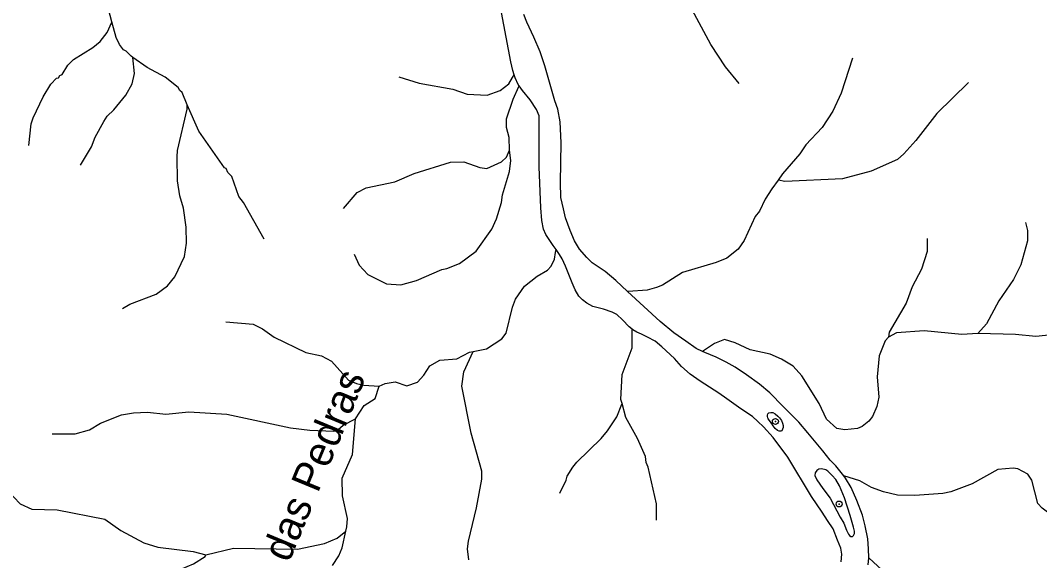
# Model space of a CAD drawing. Extents: x 393 to 446.6, y 8175.5 to 8231.
# Drawn here: x 438.18 to 443.66, y 8202.28 to 8205.18 of the extents above; entities that cross this region are included whole.
import ezdxf
from ezdxf.enums import TextEntityAlignment as Align

# ---------------------------------------------------------------- set-up
doc = ezdxf.new("R2010")
doc.units = 0
doc.header["$LTSCALE"] = 0.064
doc.header["$PDMODE"] = 32
doc.header["$PDSIZE"] = 0.032
doc.linetypes.add('LONG_DASHED', pattern=[7.5, 6, -1.5])
for name, color, linetype, lineweight in [('2', 7, 'Continuous', 25), ('7', 7, 'Continuous', 25), ('9', 7, 'LONG_DASHED', 25)]:
    doc.layers.add(name, color=color, linetype=linetype, lineweight=lineweight)
doc.layers.add('54', color=7, linetype='Continuous')
doc.layers.add('61', color=7, linetype='Continuous')

msp = doc.modelspace()

# ---------------------------------------------------------------- linework, layer by layer
at = {"layer": '2'}
for points in [[(440.8382, 8204.8883), (440.8311, 8204.9123), (440.8198, 8204.9579), (440.7579, 8205.29)], [(441.4472, 8203.724), (441.3833, 8203.7831), (441.3271, 8203.831), (441.256, 8203.8773), (441.2279, 8203.9054), (441.1882, 8203.9517), (441.1618, 8203.9963), (441.1386, 8204.0509), (441.1138, 8204.1187), (441.1022, 8204.1683), (441.089, 8204.2295), (441.0874, 8204.3088), (441.0907, 8204.5237), (441.0841, 8204.6362), (441.0725, 8204.7039), (441.0559, 8204.7486), (441.0452, 8204.7866), (441.0345, 8204.8246), (441.003, 8204.937), (440.9766, 8205.0131), (440.9435, 8205.0908), (440.9055, 8205.1718), (440.889, 8205.2131)], [(440.8641, 8204.8292), (440.8588, 8204.8359), (440.8425, 8204.8733), (440.8382, 8204.8883)], [(441.063, 8203.9487), (441.0476, 8203.97), (441.0248, 8204.0025), (441.0086, 8204.0302), (440.9955, 8204.0595), (440.9858, 8204.1051), (440.9809, 8204.1734), (440.9727, 8204.3931), (440.9727, 8204.6194), (440.9711, 8204.6682), (440.9581, 8204.7024), (440.9239, 8204.7545), (440.8832, 8204.8049), (440.8641, 8204.8292)], [(441.4709, 8203.5215), (441.4561, 8203.5338), (441.4203, 8203.5712), (441.3894, 8203.5989), (441.365, 8203.6119), (441.3178, 8203.6282), (441.2608, 8203.6428), (441.2283, 8203.6607), (441.2055, 8203.6786), (441.186, 8203.6982), (441.1648, 8203.7323), (441.1485, 8203.7698), (441.1127, 8203.8593), (441.0948, 8203.9), (441.0818, 8203.9228), (441.063, 8203.9487)], [(441.8488, 8203.4015), (441.8164, 8203.4177), (441.7602, 8203.4557), (441.6958, 8203.5004), (441.623, 8203.5615), (441.4472, 8203.724)], [(442.5955, 8202.2691), (442.5987, 8202.3114), (442.5922, 8202.3424), (442.5743, 8202.3863), (442.5515, 8202.4465), (442.5222, 8202.4921), (442.4929, 8202.5377), (442.436, 8202.6207), (442.3074, 8202.8323), (442.2293, 8202.9381), (442.1772, 8202.995), (442.1463, 8203.0243), (442.1186, 8203.0504), (442.0551, 8203.0927), (441.9813, 8203.146), (441.9379, 8203.1773), (441.837, 8203.2408), (441.7833, 8203.2782), (441.7377, 8203.3206), (441.6987, 8203.3629), (441.6319, 8203.4263), (441.5945, 8203.4556), (441.5538, 8203.4784), (441.5213, 8203.4947), (441.4968, 8203.5045), (441.4757, 8203.5175), (441.4709, 8203.5215)], [(442.6094, 8202.7315), (442.567, 8202.7862), (442.5357, 8202.8157), (442.4959, 8202.8672), (442.4149, 8202.9631), (442.367, 8203.0209), (442.3223, 8203.0656), (442.2827, 8203.1052), (442.2116, 8203.178), (442.1554, 8203.2259), (442.0859, 8203.2755), (442.0248, 8203.3169), (441.9768, 8203.3433), (441.9223, 8203.3698), (441.8627, 8203.3946), (441.8488, 8203.4015)], [(442.7439, 8202.2918), (442.7423, 8202.3398), (442.7373, 8202.3943), (442.7241, 8202.4638), (442.7092, 8202.5216), (442.6794, 8202.5993), (442.648, 8202.6688), (442.6183, 8202.72), (442.6094, 8202.7315)], [(442.7406, 8202.2538), (442.7439, 8202.2918)]]:
    msp.add_lwpolyline(points, dxfattribs=at)
for points in [[(442.2228, 8203.0112), (442.2096, 8203.0306), (442.2034, 8203.0387), (442.2003, 8203.0444), (442.1984, 8203.0513), (442.1984, 8203.0588), (442.2003, 8203.065), (442.2059, 8203.0707), (442.2172, 8203.0732), (442.2278, 8203.0725), (442.2403, 8203.0657), (442.2541, 8203.053), (442.2641, 8203.0438), (442.2741, 8203.03), (442.2804, 8203.0162), (442.2829, 8203.0024), (442.2823, 8202.9918), (442.2802, 8202.9831), (442.2754, 8202.9749), (442.2697, 8202.9718), (442.261, 8202.9724), (442.2528, 8202.9761), (442.241, 8202.9862), (442.2302, 8203.001), (442.2248, 8203.0084)], [(442.6094, 8202.4772), (442.623, 8202.4407), (442.634, 8202.4187), (442.64, 8202.4119), (442.6476, 8202.4068), (442.6561, 8202.4059), (442.6612, 8202.411), (442.6663, 8202.4229), (442.6663, 8202.4348), (442.6612, 8202.456), (442.6434, 8202.5196), (442.6128, 8202.6137), (442.5866, 8202.6789), (442.5662, 8202.712), (442.5467, 8202.7349), (442.523, 8202.7569), (442.5119, 8202.7646), (442.4888, 8202.77), (442.4746, 8202.7688), (442.4645, 8202.7612), (442.4551, 8202.7485), (442.4526, 8202.7341), (442.4636, 8202.7112), (442.4967, 8202.6637), (442.5348, 8202.612), (442.5543, 8202.5772), (442.5891, 8202.5094)]]:
    msp.add_lwpolyline(points, close=True, dxfattribs=at)
at = {"layer": '54'}
for p in [(442.2414, 8203.0245), (442.5836, 8202.5807)]:
    msp.add_point(p, dxfattribs=at)
at = {"layer": '7'}
for points in [[(438.6761, 8205.1727), (438.6578, 8205.2414), (438.6438, 8205.2614), (438.527, 8205.4287), (438.4931, 8205.587), (438.4544, 8205.6516), (438.4269, 8205.6806), (438.4109, 8205.7099)], [(442.0471, 8204.8411), (441.973, 8204.9314), (441.8939, 8205.0508), (441.7566, 8205.3092), (441.7017, 8205.3689), (441.6226, 8205.4206), (441.5613, 8205.4464), (441.5096, 8205.4577), (441.445, 8205.4577), (441.4063, 8205.4658), (441.3013, 8205.4949), (441.2787, 8205.5078), (441.2334, 8205.5546), (441.164, 8205.6709), (441.0995, 8205.726)], [(438.2297, 8204.5079), (438.2428, 8204.6245), (438.2525, 8204.6568), (438.3058, 8204.7699), (438.3478, 8204.8377), (438.3785, 8204.87), (438.3882, 8204.8716), (438.3963, 8204.8845), (438.4092, 8204.891), (438.4398, 8204.941), (438.4705, 8204.9717), (438.5739, 8205.0363), (438.6126, 8205.0686), (438.6514, 8205.117), (438.6756, 8205.1716), (438.6761, 8205.1727)], [(438.7891, 8204.9814), (438.7788, 8204.9885), (438.7532, 8205.0164), (438.7386, 8205.0234), (438.7176, 8205.0508), (438.6982, 8205.0896), (438.6761, 8205.1727)], [(438.5066, 8204.4023), (438.5658, 8204.5018), (438.5852, 8204.5535), (438.632, 8204.6375), (438.6514, 8204.6665), (438.6869, 8204.7004), (438.7515, 8204.7796), (438.7854, 8204.8409), (438.7967, 8204.8958), (438.7891, 8204.9812), (438.7891, 8204.9814)], [(439.0805, 8204.7264), (439.0537, 8204.7939), (439.0406, 8204.8037), (439.0325, 8204.8199), (438.963, 8204.8764), (438.8662, 8204.9281), (438.7891, 8204.9814)], [(442.6553, 8204.9784), (442.5947, 8204.7893), (442.5495, 8204.6924), (442.493, 8204.6052), (442.4058, 8204.5115), (442.3735, 8204.4631), (442.2798, 8204.3565), (442.2555, 8204.3227)], [(443.2782, 8204.8479), (443.1082, 8204.681), (442.9968, 8204.5357), (442.9322, 8204.463), (442.8967, 8204.434), (442.7562, 8204.371), (442.6012, 8204.329), (442.2912, 8204.3145), (442.2572, 8204.3223), (442.2555, 8204.3227)], [(438.7322, 8203.6317), (438.7718, 8203.655), (438.913, 8203.7089), (438.9744, 8203.7541), (439.0147, 8203.8026), (439.0664, 8203.9108), (439.0761, 8203.9834), (439.0745, 8204.0691), (439.0599, 8204.1724), (439.0405, 8204.237), (439.0276, 8204.3177), (439.026, 8204.4469), (439.0276, 8204.4824), (439.0805, 8204.7043), (439.0805, 8204.7264)], [(439.4939, 8204.0057), (439.3829, 8204.2015), (439.3587, 8204.2338), (439.3199, 8204.3419), (439.299, 8204.3629), (439.2893, 8204.3855), (439.2812, 8204.3887), (439.1423, 8204.5858), (439.0805, 8204.7264)], [(442.2555, 8204.3227), (442.2217, 8204.2757), (442.1862, 8204.2208), (442.1555, 8204.1563), (442.1329, 8204.1272), (442.0731, 8203.998), (442.0408, 8203.9512), (441.9811, 8203.9027), (441.923, 8203.8785), (441.7421, 8203.8252), (441.6356, 8203.7574), (441.6033, 8203.7444), (441.5516, 8203.7315), (441.4496, 8203.7242), (441.4472, 8203.724)], [(441.4173, 8203.1214), (441.4112, 8203.1432), (441.4175, 8203.2778), (441.4724, 8203.4199), (441.4714, 8203.4885), (441.4709, 8203.5215)], [(441.0824, 8202.6384), (441.1172, 8202.7094), (441.122, 8202.7304), (441.1527, 8202.7788), (441.1737, 8202.8063), (441.3045, 8202.9322), (441.34, 8202.9742), (441.3901, 8203.0501), (441.4158, 8203.1176), (441.4173, 8203.1214)], [(441.6023, 8202.4939), (441.6016, 8202.5818), (441.558, 8202.7788), (441.5467, 8202.8031), (441.5435, 8202.8354), (441.4999, 8202.9322), (441.4385, 8203.0453), (441.4173, 8203.1214)], [(442.918, 8202.157), (442.8386, 8202.2039), (442.7439, 8202.2918)]]:
    msp.add_lwpolyline(points, dxfattribs=at)
at = {"layer": '9'}
for points in [[(440.2184, 8204.8778), (440.3278, 8204.8437), (440.5076, 8204.8115), (440.5842, 8204.7845), (440.6917, 8204.7798), (440.7628, 8204.8034), (440.8082, 8204.8405), (440.829, 8204.8737), (440.8382, 8204.8883)], [(440.8126, 8204.4829), (440.8104, 8204.551), (440.7958, 8204.6058), (440.7959, 8204.6513), (440.8317, 8204.7575), (440.8625, 8204.8256), (440.8641, 8204.8292)], [(439.9197, 8204.1704), (439.9937, 8204.2552), (440.0427, 8204.2802), (440.1969, 8204.3123), (440.3009, 8204.3583), (440.4946, 8204.4192), (440.5669, 8204.4206), (440.6539, 8204.3895), (440.6907, 8204.3856), (440.7687, 8204.4214), (440.7967, 8204.4465), (440.8126, 8204.4829)], [(439.9785, 8203.9237), (440.0052, 8203.8655), (440.0516, 8203.8155), (440.1524, 8203.7642), (440.2291, 8203.7591), (440.3119, 8203.7834), (440.4482, 8203.842), (440.4758, 8203.8463), (440.544, 8203.8732), (440.6334, 8203.9404), (440.7178, 8204.0587), (440.7426, 8204.1149), (440.7699, 8204.2014), (440.775, 8204.244), (440.812, 8204.3684), (440.8189, 8204.4274), (440.8126, 8204.4829)], [(443.5861, 8204.0947), (443.5957, 8204.0509), (443.5957, 8203.9967), (443.5603, 8203.8662), (443.5215, 8203.788), (443.4428, 8203.6738), (443.3766, 8203.5496), (443.3299, 8203.497)], [(443.0564, 8204.0079), (443.0561, 8203.9386), (443.0261, 8203.8438), (442.9756, 8203.7489), (442.9434, 8203.6611), (442.8519, 8203.5045), (442.8496, 8203.4774)], [(440.6169, 8203.4016), (440.689, 8203.4158), (440.7719, 8203.4687), (440.7941, 8203.4992), (440.828, 8203.6388), (440.8444, 8203.6831), (440.8932, 8203.7524), (440.9617, 8203.8053), (441.0161, 8203.8376), (441.036, 8203.8588), (441.0538, 8203.897), (441.0602, 8203.933), (441.063, 8203.9487)], [(439.2882, 8203.5596), (439.4352, 8203.5474), (439.4858, 8203.5233), (439.5488, 8203.4772), (439.7182, 8203.3959), (439.8029, 8203.3776), (439.8557, 8203.3497), (439.9482, 8203.2463), (439.9909, 8203.228), (440.0298, 8203.2197), (440.1113, 8203.2143)], [(443.3299, 8203.497), (443.2424, 8203.4914), (443.041, 8203.5118), (442.892, 8203.5019), (442.8496, 8203.4774)], [(442.8496, 8203.4774), (442.8318, 8203.4588), (442.799, 8203.3771), (442.7886, 8203.2637), (442.7965, 8203.155), (442.7866, 8203.1046), (442.763, 8203.0508), (442.7439, 8203.0266), (442.7071, 8202.9982), (442.6818, 8202.9871), (442.6143, 8202.9791), (442.5718, 8202.9859), (442.5155, 8203.0377), (442.4769, 8203.1205), (442.3827, 8203.2701), (442.3375, 8203.3215), (442.275, 8203.36), (442.2136, 8203.3858), (442.1065, 8203.4089), (442.0251, 8203.447), (441.9671, 8203.4646), (441.9149, 8203.4436), (441.8488, 8203.4015)], [(443.7603, 8203.4935), (443.641, 8203.4816), (443.5308, 8203.4925), (443.3307, 8203.497), (443.3299, 8203.497)], [(440.1113, 8203.2143), (440.1437, 8203.2289), (440.1983, 8203.2372), (440.2614, 8203.2167), (440.319, 8203.2351), (440.3529, 8203.274), (440.3843, 8203.3244), (440.4387, 8203.3542), (440.5294, 8203.3619), (440.5978, 8203.3979), (440.6169, 8203.4016)], [(440.5943, 8202.2812), (440.5875, 8202.3403), (440.5921, 8202.3817), (440.6358, 8202.56), (440.6633, 8202.7151), (440.6632, 8202.757), (440.6067, 8202.9619), (440.557, 8203.2149), (440.5667, 8203.291), (440.6169, 8203.4016)], [(439.9848, 8203.0386), (440.0315, 8203.111), (440.0906, 8203.1488), (440.1113, 8203.2143)], [(438.3547, 8202.9581), (438.4794, 8202.9583), (438.5548, 8202.9802), (438.6143, 8203.016), (438.7283, 8203.0594), (438.7921, 8203.0711), (438.8675, 8203.0741), (438.9652, 8203.063), (439.0888, 8203.0757), (439.2932, 8203.063), (439.6349, 8202.9903), (439.7404, 8202.9774), (439.8677, 8202.9724), (439.8924, 8202.9817), (439.9194, 8203.004), (439.9848, 8203.0386)], [(439.9338, 8202.4352), (439.9389, 8202.4585), (439.9414, 8202.5025), (439.9157, 8202.6238), (439.9141, 8202.7205), (439.9686, 8202.8468), (439.9848, 8203.0386)], [(444.2171, 8202.3957), (444.1628, 8202.3937), (444.1, 8202.404), (444.0398, 8202.4413), (444.0025, 8202.4558), (443.9253, 8202.4574), (443.8479, 8202.4496), (443.7949, 8202.4686), (443.675, 8202.5592), (443.6521, 8202.5836), (443.6197, 8202.7095), (443.5983, 8202.7404), (443.5448, 8202.7694), (443.5184, 8202.7726), (443.437, 8202.7655), (443.2981, 8202.6897), (443.1849, 8202.6469), (443.1412, 8202.6376), (442.9913, 8202.627), (442.8979, 8202.6286), (442.8224, 8202.6466), (442.7585, 8202.6703), (442.6955, 8202.7059), (442.6094, 8202.7315)], [(438.1155, 8202.6532), (438.1831, 8202.5818), (438.2449, 8202.5531), (438.3811, 8202.5492), (438.6377, 8202.4994), (438.7237, 8202.4391), (438.8472, 8202.3724), (438.9232, 8202.3492), (439.112, 8202.3251), (439.1804, 8202.3066)], [(439.1804, 8202.3066), (439.3302, 8202.3427), (439.6733, 8202.3382), (439.8179, 8202.3688), (439.8867, 8202.3978), (439.9338, 8202.4352)], [(439.8622, 8202.2497), (439.8959, 8202.3014), (439.9141, 8202.3443), (439.9338, 8202.4352)], [(437.4373, 8202.1354), (437.4625, 8202.1389), (437.4894, 8202.1331), (437.5824, 8202.1038), (437.7019, 8202.0279), (437.7665, 8201.9698), (437.8262, 8201.9246), (437.8569, 8201.91), (437.9587, 8201.8762), (438.1315, 8201.8842), (438.2703, 8201.9165), (438.3527, 8201.9472), (438.4173, 8201.9827), (438.5707, 8202.107), (438.7144, 8202.1813), (438.7968, 8202.1975), (438.8597, 8202.1959), (439.0131, 8202.2152), (439.1149, 8202.2588), (439.1778, 8202.2976), (439.1804, 8202.3066)]]:
    msp.add_lwpolyline(points, dxfattribs=at)

# ---------------------------------------------------------------- texts
at = {"layer": '61'}
msp.add_text('Córrego das Pedras', height=0.16, rotation=67.49, dxfattribs=at).set_placement((439.6753, 8202.3767), align=Align.CENTER)

doc.saveas('drawing.dxf')
